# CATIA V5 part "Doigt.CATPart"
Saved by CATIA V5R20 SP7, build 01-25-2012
Part number: Doigt
Bounding box of the stored display mesh (mm): x -8.948 to 8.948, y 0 to 33.75, z -8.948 to 8.948
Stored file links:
  F:\Travaux\Modélisations\CFAO_2011\MMS\MMS_GR1\AA_OK\bmadec\Catia\Doigt.CATPart
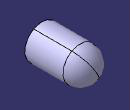
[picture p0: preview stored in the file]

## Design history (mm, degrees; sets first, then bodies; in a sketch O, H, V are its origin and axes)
Body1 (main body)
  Sketch1 on yz-plane, origin (0, 0, 0), H (0, 1, 0), V (0, 0, 1)
    line L1 (0, 0) -> (0, 0.5)
    line L2 (0, 0.5) -> (4.75, 9)
    line L3 (4.75, 9) -> (24.75, 9)
    arc A1 centre (24.75, 0) radius 9 from (24.75, 9) to (33.75, 0) cw
    point P4 (24.75, 0)
    point P5 (33.75, 0)
    line L4 (33.75, 0) -> (0, 0)
    radius A1 = 9
    length L1 = 0.5
    length L4 = 33.75
    length L3 = 20
    vertical: L1 V
    horizontal: L3 H, L4 H
    coincidence: P5 H, P4 L4
    tangency: A1 L3
  Shaft1: profile Sketch1, axis Sketch1.L4, angle 360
